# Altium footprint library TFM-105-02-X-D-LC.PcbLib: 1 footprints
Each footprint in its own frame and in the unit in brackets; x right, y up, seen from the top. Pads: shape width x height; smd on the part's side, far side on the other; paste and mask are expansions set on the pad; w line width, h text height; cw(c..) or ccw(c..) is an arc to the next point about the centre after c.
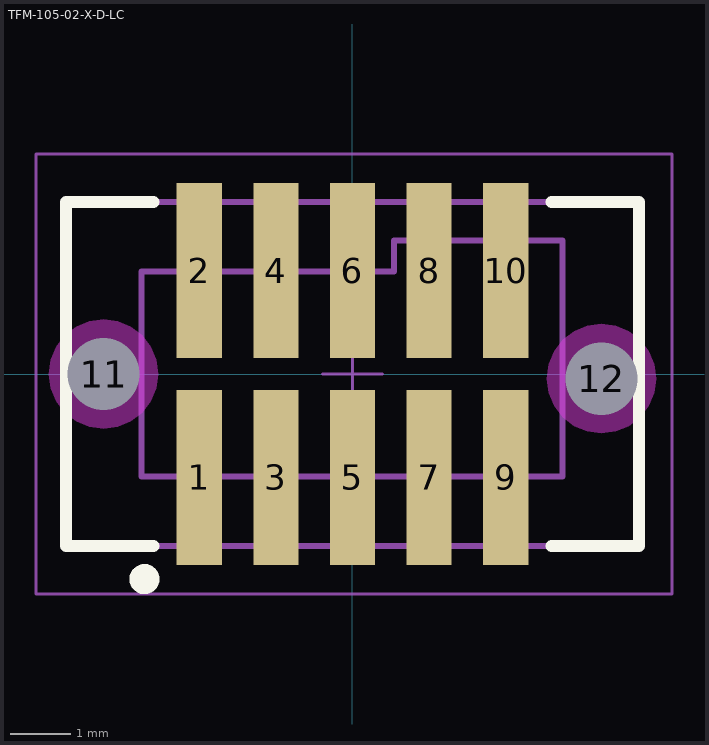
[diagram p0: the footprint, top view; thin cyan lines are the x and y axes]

## TFM-105-02-X-D-LC [mm] "1.27mm pitch, 10 pin, terminal strip; w/locking clips, SMT"
height 5.72
pads (12):
  rect 0.75x2.9 smd mask+0: 1(-2.54,-1.714) 2(-2.54,1.714) 3(-1.27,-1.714) 4(-1.27,1.714) 5(0,-1.714) 6(0,1.714) 7(1.27,-1.714) 8(1.27,1.714) 9(2.54,-1.714) 10(2.54,1.714)
  round 1 hole 1.2 unplated mask+0: 11(-4.127,0) 12(4.127,-0.076)
Top Overlay:
  circle w0.25: c-3.45,-3.4 r0.125
  lines w0.2: -3.3,-2.85 -4.75,-2.85 -4.75,2.85 -3.3,2.85 ; 3.3,-2.85 4.75,-2.85 4.75,2.85 3.3,2.85
Keep-Out Layer:
  pour cut-out: 5.035,-0.076 5.005,0.159 4.914,0.378 4.77,0.566 4.582,0.71 4.363,0.801 4.128,0.831 3.893,0.801 3.674,0.71 3.486,0.566 3.342,0.378 3.251,0.159 3.22,-0.076 3.251,-0.311 3.342,-0.53 3.486,-0.718 3.674,-0.862 3.893,-0.953 4.128,-0.984 4.363,-0.953 4.582,-0.862 4.77,-0.718 4.914,-0.53 5.005,-0.311
  pour cut-out: -3.22,0 -3.251,0.235 -3.342,0.454 -3.486,0.642 -3.674,0.786 -3.893,0.877 -4.128,0.908 -4.363,0.877 -4.582,0.786 -4.77,0.642 -4.914,0.454 -5.005,0.235 -5.035,0 -5.005,-0.235 -4.914,-0.454 -4.77,-0.642 -4.582,-0.786 -4.363,-0.877 -4.128,-0.908 -3.893,-0.877 -3.674,-0.786 -3.486,-0.642 -3.342,-0.454 -3.251,-0.235
Mechanical 12:
  lines w0.001: -4.75,-2.85 -4.75,2.85 4.75,2.85 4.75,-2.85 -4.75,-2.85 ; -3.5,-1.702 -3.5,1.702 0.686,1.702 0.686,2.21 3.48,2.21 3.48,-1.702 -3.5,-1.702
Mechanical 13:
  lines w0.1: -4.75,-2.85 -4.75,2.85 4.75,2.85 4.75,-2.85 -4.75,-2.85 ; -3.5,-1.702 -3.5,1.702 0.686,1.702 0.686,2.21 3.48,2.21 3.48,-1.702 -3.5,-1.702
  text ".Designator" at 0,-0.127 h1.52
Mechanical 15:
  lines w0.05: -0.5,0 0.5,0 ; 0,-0.5 0,0.5 ; -5.25,-3.65 -5.25,3.65 5.3,3.65 5.3,-3.65 -5.25,-3.65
